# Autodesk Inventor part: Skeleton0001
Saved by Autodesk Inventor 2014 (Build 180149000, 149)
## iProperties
Created: 2009-11
Part Number: Skeleton0001
Document SubType Name: Modeling
Designer: pokornp
Density: 1 g/cm^3
Material: Generic
Appearance: Default
_SkeletonDoc: Frame Skeleton File
_Version: 15.0.0
Author: pokornp
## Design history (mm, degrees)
sketch "Reference Skeleton"
